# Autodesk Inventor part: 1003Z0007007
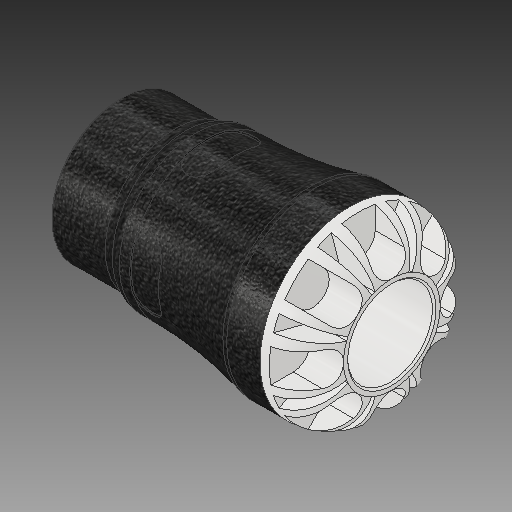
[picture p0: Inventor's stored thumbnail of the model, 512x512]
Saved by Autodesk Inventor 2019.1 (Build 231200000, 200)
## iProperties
Created: 2016-12
Part Number: 1003Z0007007
Material: PVC-Piping
Description: PLASSON FEMALE ADAPTOR 3/4''CTS x 3/4''NPT SERIES 1
Document SubType Name: Modeling
Designer: KIM
Mass: 664.23 g
Surface Area: 733.008 cm^2
Volume: 474.45 cm^3
Density: 1.4 g/cm^3
Appearance: Black Cast
Author: KIM
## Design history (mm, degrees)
derived "1003Z.ipt"
feature "Solid1::1003Z.ipt"
tag "TaggingFeature1"
body "Solid1"
other parameters: "d0" = 70.866, "d1" = 20.16252, "d2" = 22.1, "d3" = 25.21125, "d4" = 46.99, "d6" = 48.006, "d8" = 39.9415, "d13" = 8.7115, "d14" = 8.7115, "d15" = 0, "d17" = 360 deg, "d19" = 8 deg, "d20" = 0.442, "d21" = 0.442, "d22" = 8 deg, "d24" = 0, "d26" = 360 deg, "d32" = 4.699, "d33" = 4.699, "d39" = 0.55893, "d42" = 18.631, "d43" = 36.6522, "d46" = 1.84167, "d47" = 18.034, "d48" = 17.69945, "d50" = 1.59258, "d51" = 0.4699, "d54" = 7.735, "d55" = 4.862, "d57" = 15.18216, "d58" = 0, "d68" = 360 deg, "d72" = 0.442, "d74" = 0, "d76" = 6.57475, "d_" = 22.1, "E_" = 46.99, "H_" = 70.866, "l_" = 48.006, "G_" = 18.631, "l_2" = 18.034, "d9" = 10.88937, "d11" = 46.99, "d12" = 25.21125, "d49" = 4.826
